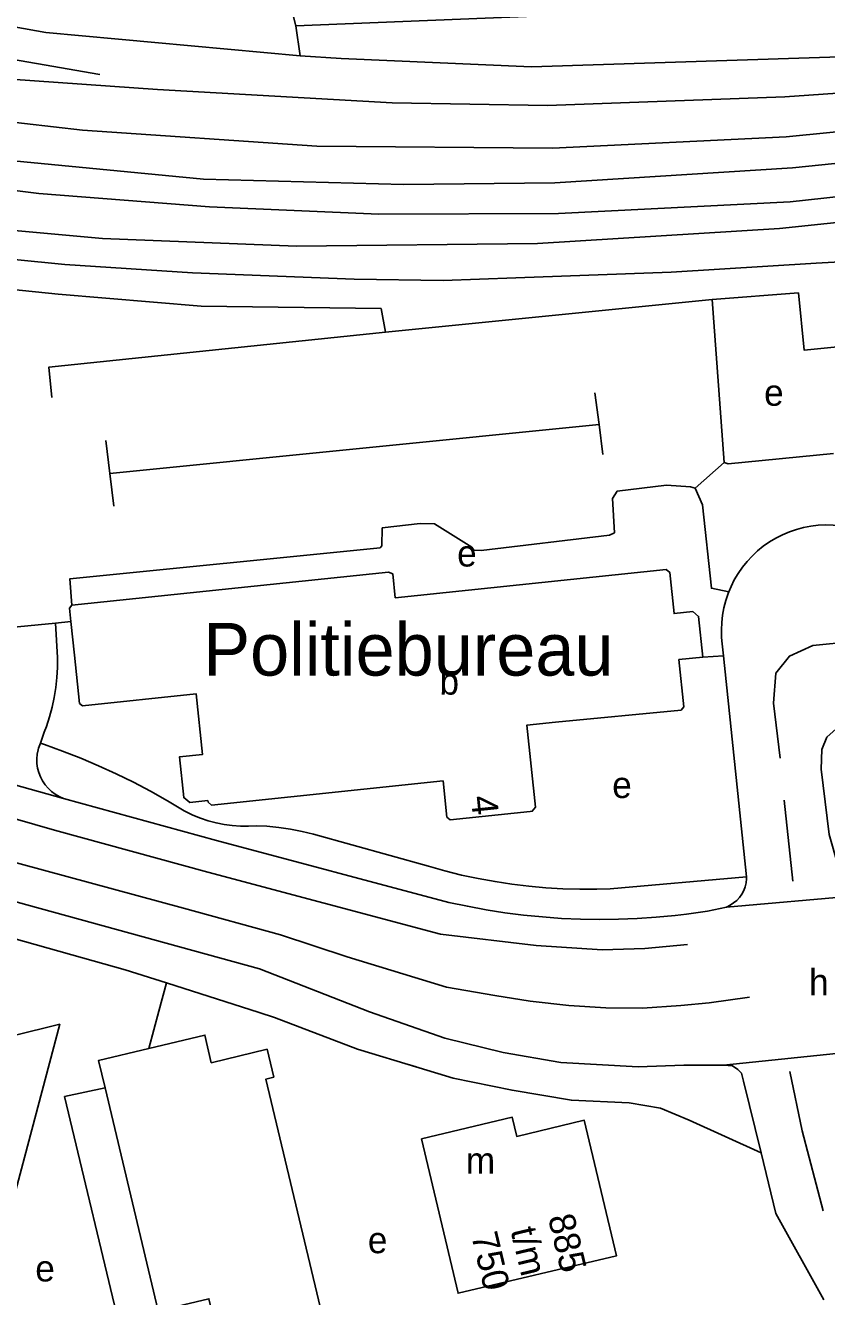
# Model space of a CAD drawing. Extents: x 160673 to 161924, y 382258 to 384145.
# Drawn here: x 160877.2 to 160999.1, y 383510.1 to 383703.4 of the extents above; entities that cross this region are included whole.
import ezdxf

# ---------------------------------------------------------------- set-up
doc = ezdxf.new("R2010")
doc.units = 0
for name, color, linetype in [('BLT_Basislijn', 7, 'Continuous'), ('BLT_Bebouwing', 7, 'Continuous'), ('BLT_Bebouwing_beschrifting', 7, 'Continuous'), ('BLT_Centroide', 7, 'Continuous'), ('BLT_Huisnummer', 7, 'Continuous'), ('BLT_Huisnummer_reeks', 7, 'Continuous'), ('BLT_Spoorlijn', 7, 'Continuous'), ('BLT_Vlakafsluiter', 7, 'Continuous')]:
    doc.layers.add(name, color=color, linetype=linetype)

msp = doc.modelspace()

# ---------------------------------------------------------------- linework, layer by layer
at = {"layer": 'BLT_Basislijn'}
for p, q in [((160910.72, 383733.91), (160918.31, 383703.37)), ((160918.31, 383703.37), (160984.76, 383706.08)), ((160951.82, 383665.07), (160940.73, 383664.63)), ((160931.98, 383656.8), (160931.32, 383660.4)), ((160931.98, 383656.8), (160981.68, 383661.77)), ((160983.54, 383636.96), (160981.68, 383661.77)), ((160963.85, 383647.58), (160964.47, 383642.76)), ((160890, 383635.31), (160964.47, 383642.76)), ((160964.47, 383642.76), (160965.06, 383638.19)), ((160889.4, 383640.31), (160890, 383635.31)), ((160890, 383635.31), (160890.61, 383630.32)), ((160979.1, 383633.04), (160983.54, 383636.96)), ((160874.92, 383611.89), (160881.75, 383612.54)), ((160881.75, 383612.54), (160884.1, 383612.77)), ((160882.06, 383607.32), (160881.75, 383612.54)), ((160983.21, 383609.4), (160983.4, 383607.54)), ((160980.28, 383607.37), (160983.4, 383607.54)), ((160983.4, 383607.54), (160986.91, 383573.95)), ((160879.45, 383594.29), (160880.03, 383595.94)), ((160879.18, 383593.53), (160879.45, 383594.29)), ((160882.94, 383585.87), (160906.27, 383579.46)), ((160992.66, 383585.6), (160993.98, 383573.28)), ((160881.61, 383581.05), (160904.94, 383574.64)), ((160863.02, 383579.54), (160901.21, 383569.2)), ((160906.27, 383579.46), (160941.62, 383570.06)), ((160921.04, 383580.43), (160938.53, 383575.55)), ((160904.94, 383574.64), (160940.34, 383565.23)), ((160966.15, 383572.13), (160986.91, 383573.95)), ((160980.96, 383568.74), (160977.77, 383568.27)), ((160980.96, 383568.74), (160983.88, 383569.35)), ((160873.42, 383565.14), (160885.87, 383561.63)), ((160954.91, 383563.52), (160940.34, 383565.23)), ((160995.4, 383535.32), (160993.52, 383544.34)), ((160986.45, 383542.86), (160989.13, 383531.95)), ((160995.4, 383535.32), (160998.59, 383523.14))]:
    msp.add_line(p, q, dxfattribs=at)
for points in [[(160827.47, 383712.33), (160848.19, 383708.12), (160880.3, 383702.37), (160918.98, 383698.8)], [(160918.31, 383703.37), (160918.98, 383698.8)], [(160954.18, 383697.13), (161005.83, 383698.79), (161041.27, 383699.58), (161080.72, 383704.46)], [(160918.98, 383698.8), (160925.23, 383698.39), (160954.18, 383697.13)], [(160997.5, 383667.29), (161010.21, 383668), (161087.45, 383676.39), (161092.55, 383679.11), (161103.37, 383680.29)], [(160940.73, 383664.63), (160927.19, 383664.82), (160902.61, 383665.8), (160883.17, 383667.06), (160860.14, 383669.36), (160849.53, 383670.59), (160810.77, 383676.62), (160795.38, 383678.83)], [(160838.61, 383668.19), (160858.92, 383664.92), (160882.17, 383662.58), (160903.94, 383660.75), (160931.32, 383660.4)], [(160997.5, 383667.29), (160975.43, 383665.9), (160951.82, 383665.07)], [(161003.32, 383654.81), (160995.71, 383654.03), (160994.81, 383662.76), (160981.68, 383661.77)], [(160931.98, 383656.8), (160880.73, 383651.45), (160881.21, 383646.83)], [(160983.54, 383636.96), (160984.11, 383636.75), (161000.18, 383638.35)], [(160979.1, 383633.04), (160978.39, 383633.27), (160974.72, 383633.52), (160967.23, 383632.59), (160966.54, 383631.46), (160966.81, 383626.28), (160966.08, 383625.91), (160946.51, 383623.59), (160945.44, 383623.62), (160945.09, 383624.07), (160939.44, 383627.62), (160937.27, 383627.7), (160931.48, 383627), (160931.42, 383624.27), (160931.15, 383623.99), (160883.91, 383619.25), (160884.25, 383615.27)], [(160984.23, 383617.3), (160981.57, 383617.84), (160980.23, 383630.53), (160979.1, 383633.04)], [(161001.33, 383627.34), (161000.12, 383627.45), (160998.98, 383627.48), (160997.85, 383627.43), (160996.72, 383627.29), (160995.61, 383627.08), (160994.51, 383626.79), (160993.44, 383626.42), (160992.39, 383625.98), (160991.38, 383625.46), (160990.41, 383624.88), (160989.48, 383624.23), (160988.6, 383623.51), (160987.77, 383622.73), (160987, 383621.9), (160986.29, 383621.02), (160985.64, 383620.08), (160985.06, 383619.11), (160984.56, 383618.09), (160984.23, 383617.3)], [(160752.56, 383620.7), (160758.95, 383618.07), (160765.44, 383615.49), (160771.96, 383612.98), (160776.48, 383611.29), (160881.61, 383581.05)], [(160984.23, 383617.3), (160984.12, 383617.05), (160983.76, 383615.97), (160983.47, 383614.87), (160983.27, 383613.76), (160983.14, 383612.63), (160983.09, 383611.5), (160983.12, 383610.36), (160983.21, 383609.4)], [(160992.02, 383592.01), (160991.02, 383600.36), (160991.4, 383604.9), (160993.46, 383607.52), (160997.02, 383609.12), (161003.14, 383609.75)], [(160882.06, 383607.32), (160882.05, 383605.79), (160881.97, 383604.26), (160881.8, 383602.74), (160881.56, 383601.24), (160881.24, 383599.74), (160880.84, 383598.27), (160880.36, 383596.82), (160880.03, 383595.94)], [(161007.68, 383571.44), (161005.15, 383571.64), (161003.33, 383572.56), (161001.86, 383573.86), (161000.88, 383575.55), (160999.48, 383580.36), (160998.3, 383590.33), (160998.41, 383593.33), (160999.16, 383595.21), (161001.55, 383597.34), (161004.34, 383598.2)], [(160882.94, 383585.87), (160882.3, 383586.16), (160881.69, 383586.51), (160881.12, 383586.93), (160880.61, 383587.41), (160880.15, 383587.94), (160879.76, 383588.52), (160879.44, 383589.15), (160879.19, 383589.8), (160879.01, 383590.48), (160878.92, 383591.18), (160878.9, 383591.88), (160878.96, 383592.58), (160879.11, 383593.27), (160879.18, 383593.53)], [(160901.33, 383584), (160898.8, 383585.51), (160896.22, 383586.95), (160893.61, 383588.32), (160890.97, 383589.62), (160888.29, 383590.84), (160885.58, 383592), (160882.83, 383593.08), (160880.06, 383594.08), (160879.45, 383594.29)], [(160912.38, 383581.72), (160911.13, 383581.65), (160909.89, 383581.65), (160908.65, 383581.74), (160907.42, 383581.9), (160906.2, 383582.15), (160904.99, 383582.47), (160903.81, 383582.86), (160902.66, 383583.34), (160901.55, 383583.88), (160901.33, 383584)], [(160921.04, 383580.43), (160919.29, 383580.85), (160917.51, 383581.19), (160915.73, 383581.45), (160913.93, 383581.63), (160912.38, 383581.72)], [(160938.53, 383575.55), (160941.03, 383574.84), (160943.56, 383574.22), (160946.09, 383573.67), (160948.65, 383573.21), (160951.21, 383572.82), (160953.79, 383572.51), (160956.38, 383572.28), (160958.97, 383572.13), (160961.57, 383572.06), (160964.16, 383572.07), (160966.15, 383572.13)], [(160941.01, 383549.42), (160929.52, 383553.39), (160912.82, 383559.96), (160900.62, 383563.32), (160864.24, 383573.3)], [(160983.88, 383569.35), (160984.43, 383569.65), (160984.95, 383569.97), (160985.43, 383570.36), (160985.85, 383570.82), (160986.21, 383571.32), (160986.5, 383571.86), (160986.71, 383572.44), (160986.86, 383573.04), (160986.92, 383573.65), (160986.91, 383573.95)], [(160941.62, 383570.06), (160944.45, 383569.46), (160947.29, 383568.93), (160950.14, 383568.49), (160953, 383568.12), (160955.88, 383567.84), (160958.76, 383567.63), (160961.64, 383567.5), (160964.53, 383567.46), (160967.42, 383567.49), (160970.3, 383567.6), (160973.18, 383567.8), (160976.06, 383568.07), (160977.77, 383568.27)], [(160941.24, 383557.17), (160926.12, 383561.78), (160915.99, 383565.1), (160901.21, 383569.2)], [(160977.92, 383563.63), (160971.46, 383563.02), (160964.93, 383562.85), (160954.91, 383563.52)], [(160885.87, 383561.63), (160892.35, 383559.8), (160898.64, 383557.8)], [(160895.93, 383547.83), (160897.47, 383553.51), (160898.64, 383557.8)], [(160898.64, 383557.8), (160912.73, 383553.32)], [(160987.37, 383555.62), (160981.26, 383554.79), (160976.92, 383554.4), (160971.07, 383553.95), (160965.49, 383554.01), (160959.87, 383554.4), (160954.01, 383555.02), (160948.61, 383555.92), (160941.24, 383557.17)], [(160912.73, 383553.32), (160915.09, 383552.57)], [(160915.09, 383552.57), (160927.71, 383547.75), (160937.12, 383544.89)], [(160941.01, 383549.42), (160949.88, 383547.23), (160958.64, 383545.72), (160970.41, 383545.04), (160977.39, 383545.31), (160983.41, 383545.31)], [(160935.62, 383545.35), (160936.65, 383545.04)], [(160937.12, 383544.89), (160942.25, 383543.33)], [(160983.41, 383545.31), (160984.78, 383545.18), (160985.6, 383544.63), (160986.15, 383544.08), (160986.45, 383542.86)], [(160942.25, 383543.33), (160951.25, 383541.48), (160960.28, 383539.97), (160969.04, 383539.56), (160973.83, 383538.74), (160978.21, 383536.96), (160989.13, 383531.95)], [(160842.89, 383491.44), (160857.49, 383494.91), (160858.08, 383492.7), (160889.67, 383500.12), (160891.88, 383503.94), (160883.12, 383540.53), (160889.29, 383541.87)], [(160989.13, 383531.95), (160991.39, 383522.74), (160998.69, 383509.61)]]:
    msp.add_lwpolyline(points, dxfattribs=at)
at = {"layer": 'BLT_Bebouwing'}
for points in [[(160884.25, 383615.27), (160932.45, 383620.3), (160933.08, 383620.02), (160933.46, 383616.38), (160974.68, 383620.69), (160975.23, 383620.24), (160975.89, 383613.98), (160978.74, 383614.28), (160979.63, 383613.55), (160980.28, 383607.37)], [(160884.1, 383612.77), (160883.88, 383614.81), (160884.25, 383615.27)], [(160885.86, 383599.96), (160885.4, 383600.33), (160884.63, 383607.66), (160884.1, 383612.77)], [(160980.28, 383607.37), (160976.62, 383606.99), (160977.37, 383599.82), (160976.95, 383599.28), (160957.83, 383597.45)], [(160954.01, 383583.88), (160941.84, 383582.61), (160941.32, 383583.04), (160940.74, 383588.53), (160905.51, 383584.85), (160904.96, 383585.3), (160904.93, 383585.55), (160902.18, 383585.26), (160901.27, 383586), (160900.62, 383592.18), (160904.14, 383592.55), (160903.18, 383601.77), (160885.86, 383599.96)], [(160957.83, 383597.45), (160953.5, 383597.03), (160954.8, 383584.53), (160954.3, 383583.91), (160954.01, 383583.88)], [(160867.86, 383547.96), (160882.4, 383551.52), (160871.13, 383509.23), (160858.45, 383512.62)], [(160895.93, 383547.83), (160904.48, 383549.87), (160905.46, 383545.68), (160913.94, 383547.72)], [(160889.29, 383541.87), (160888.3, 383546.02), (160895.93, 383547.83)], [(160913.94, 383547.72), (160914.96, 383543.48), (160913.77, 383543.19), (160922.57, 383506.21), (160918.01, 383505.13), (160921.27, 383491.7), (160924.79, 383492.55), (160924.95, 383492.07), (160991.2, 383507.82)], [(160844.62, 383482.96), (160911.11, 383498.75), (160909.88, 383503.98), (160906.7, 383503.19), (160905.09, 383509.78), (160897.39, 383507.93), (160889.29, 383541.87)]]:
    msp.add_lwpolyline(points, dxfattribs=at)
msp.add_lwpolyline([(160937.45, 383534.09), (160951.26, 383537.37), (160951.95, 383534.46), (160962.23, 383536.92), (160967.14, 383516.32), (160943.02, 383510.6)], close=True, dxfattribs=at)
at = {"layer": 'BLT_Spoorlijn'}
for points in [[(160888.5, 383695.98), (160832.94, 383705.59), (160805.98, 383710.64)], [(161173.49, 383712.07), (161170.71, 383711.45), (161140.01, 383706.48), (161083.88, 383700.28), (161034.33, 383695.48), (160992.74, 383692.56), (160956.62, 383691.24)], [(160957.39, 383684.76), (160992.98, 383686.48), (161034.86, 383690.67), (161083.43, 383695.8), (161139.72, 383702.01), (161171.88, 383706.21), (161175.06, 383706.95)], [(160810.45, 383702.83), (160856.18, 383696.58), (160897.27, 383693.67), (160932.99, 383691.66), (160956.62, 383691.24)], [(161176.28, 383702.97), (161172.71, 383702.2), (161140.05, 383697.57), (161082.94, 383691.29), (161035.99, 383686.07), (160993.93, 383681.76), (160957.76, 383679.51)], [(160808.69, 383698.88), (160827.84, 383695.56), (160847.92, 383692.06), (160863.75, 383690.03), (160885.85, 383687.51), (160921.52, 383685.06), (160957.39, 383684.76)], [(160958.31, 383674.84), (160993.55, 383676.62), (161035.91, 383681.22), (161082.7, 383686.23), (161140.28, 383692.48), (161174.01, 383697.7), (161177.65, 383698.49)], [(160787.69, 383685.98), (160798.55, 383683.51), (160830.88, 383677.77), (160863.18, 383673.34), (160888.88, 383671.04), (160918.45, 383669.84), (160955.11, 383670.29), (160991.96, 383672.56), (161075.17, 383681.29), (161131.02, 383687.39), (161179.48, 383692.52)], [(160809.8, 383691.88), (160844.05, 383686.53), (160875.35, 383682.85), (160904.27, 383680.06), (160934.72, 383679.23), (160957.76, 383679.51)], [(160804.27, 383689.3), (160830.05, 383684.14), (160855.65, 383680.82), (160879.22, 383677.89), (160905.19, 383675.87), (160930.97, 383674.75), (160958.31, 383674.84)]]:
    msp.add_lwpolyline(points, dxfattribs=at)
at = {"layer": 'BLT_Vlakafsluiter'}
for p, q in [((160860.01, 383592.29), (160882.94, 383585.87)), ((160983.88, 383569.35), (161007.68, 383571.44)), ((160983.41, 383545.31), (161009.39, 383548.02))]:
    msp.add_line(p, q, dxfattribs=at)

# ---------------------------------------------------------------- texts
at = {"layer": 'BLT_Bebouwing_beschrifting'}
msp.add_text('Politiebureau', height=8, dxfattribs=at).set_placement((160904.23, 383604.55))
at = {"layer": 'BLT_Centroide'}
for s, p in [('e', (160989.6, 383645.59)), ('e', (160942.88, 383621.14)), ('b', (160940.19, 383601.66)), ('e', (160966.48, 383585.93)), ('h', (160996.44, 383555.94)), ('m', (160944.21, 383528.8)), ('e', (160929.29, 383516.7)), ('e', (160878.67, 383512.4))]:
    msp.add_text(s, height=4, dxfattribs=at).set_placement(p)
at = {"layer": 'BLT_Huisnummer'}
msp.add_text('4', height=4, rotation=275.9653, dxfattribs=at).set_placement((160944.95, 383586.13))
at = {"layer": 'BLT_Huisnummer_reeks'}
for s, p in [('885', (160956.68, 383522.17)), ('750', (160945, 383519.42)), ('t/m', (160950.99, 383520.19))]:
    msp.add_text(s, height=4, rotation=283.4, dxfattribs=at).set_placement(p)

doc.saveas('drawing.dxf')
